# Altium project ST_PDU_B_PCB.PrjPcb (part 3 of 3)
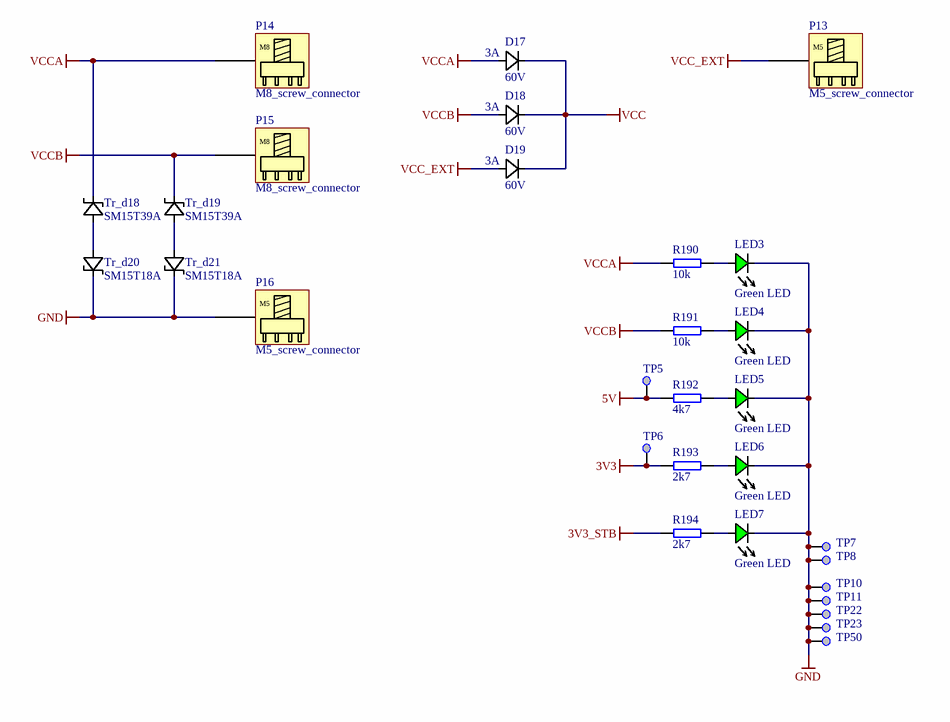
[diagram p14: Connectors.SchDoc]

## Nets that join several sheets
3V3: U_GroupA/U_VNF1248+8F8_A1 (C41A.2 R75A.1 U5A.1), U_GroupA/U_VNF1248+5F8_A1 (C51A.2 R94A.1 U6A.1), U_GroupA/U_VNF1248+3F8_A1 (C31A.2 R55A.1 U4A.1), U_GroupA/U_VNF1248+3F8_A2 (C31B.2 R55B.1 U4B.1), U_GroupA/U_VNF1248+3F8_A3 (C31C.2 R55C.1 U4C.1), U_GroupA/U_VNF9D1M5Q_A1 (C1A.2 D1A.A R1A.1), U_GroupA/U_VNF9D1M5Q_A2 (C1B.2 D1B.A R1B.1), U_GroupA/U_L99SP08_A1 (C58A.2 R101A.1), VNF9Q20SF (C15.2 D5.A R29.1), U_GroupB/U_VNF1248+8F8_B1 (C41B.2 R75B.1 U5B.1), U_GroupB/U_VNF1248+5F8_B1 (C51B.2 R94B.1 U6B.1), U_GroupB/U_VNF1248+3F8_B1 (C31D.2 R55D.1 U4D.1), U_GroupB/U_VNF1248+3F8_B2 (C31E.2 R55E.1 U4E.1), U_GroupB/U_VNF1248+3F8_B3 (C31F.2 R55F.1 U4F.1), U_GroupB/U_VNF9D1M5Q_B1 (C1C.2 D1C.A R1C.1), U_GroupB/U_VNF9D1M5Q_B2 (C1D.2 D1D.A R1D.1), U_GroupB/U_L99SP08_B1 (C58B.2 R101B.1), U_GroupB/U_VNF9D5SF_B1 (C8A.2 D2A.A R15A.1), U_GroupB/U_VNF9D5SF_B2 (C8B.2 D2B.A R15B.1), MCU (7 pins), PMIC (32 pins), Ethernet (18 pins), Connectors (R193.2 TP6.1)
3V3_STB: PMIC (6 pins), Connectors (R194.2)
5V: PMIC (C92.2 U9.3 U9.28), Connectors (R192.1 TP5.1)
GND: U_GroupA/U_VNF1248+8F8_A1 (11 pins), U_GroupA/U_VNF1248+5F8_A1 (11 pins), U_GroupA/U_VNF1248+3F8_A1 (11 pins), U_GroupA/U_VNF1248+3F8_A2 (11 pins), U_GroupA/U_VNF1248+3F8_A3 (11 pins), U_GroupA/U_VNF9D1M5Q_A1 (7 pins), U_GroupA/U_VNF9D1M5Q_A2 (7 pins), U_GroupA/U_L99SP08_A1 (8 pins), VNF9Q20SF (10 pins), U_GroupB/U_VNF1248+8F8_B1 (11 pins), U_GroupB/U_VNF1248+5F8_B1 (11 pins), U_GroupB/U_VNF1248+3F8_B1 (11 pins), U_GroupB/U_VNF1248+3F8_B2 (11 pins), U_GroupB/U_VNF1248+3F8_B3 (11 pins), U_GroupB/U_VNF9D1M5Q_B1 (7 pins), U_GroupB/U_VNF9D1M5Q_B2 (7 pins), U_GroupB/U_L99SP08_B1 (8 pins), U_GroupB/U_VNF9D5SF_B1 (8 pins), U_GroupB/U_VNF9D5SF_B2 (8 pins), MCU (21 pins), PMIC (69 pins), Ethernet (27 pins), Connectors (15 pins)
VCC: PMIC (16 pins), Ethernet (R187.2), Connectors (D17.C D18.C D19.C)
VCC_EXT: MCU (R143.2), Connectors (D19.A P13.1)
VCCA: GroupA (Tr_d3.C Tr_d4.C), U_GroupA/U_VNF1248+8F8_A1 (D9A.A R60A.2), U_GroupA/U_VNF1248+5F8_A1 (D10A.A R82A.2), U_GroupA/U_VNF1248+3F8_A1 (D8A.A R43A.2), U_GroupA/U_VNF1248+3F8_A2 (D8B.A R43B.2), U_GroupA/U_VNF1248+3F8_A3 (D8C.A R43C.2), U_GroupA/U_VNF9D1M5Q_A1 (C3A.2 JP1A.3 JP2A.3 U1A.0), U_GroupA/U_VNF9D1M5Q_A2 (C3B.2 JP1B.3 JP2B.3 U1B.0), U_GroupA/U_L99SP08_A1 (D14A.A), VNF9Q20SF (C17.2 D4.1 U3.0), MCU (R144.2), Connectors (D17.A P14.1 R190.2 Tr_d18.C)
VCCB: GroupB (Tr_d10.C Tr_d13.C), U_GroupB/U_VNF1248+8F8_B1 (D9B.A R60B.2), U_GroupB/U_VNF1248+5F8_B1 (D10B.A R82B.2), U_GroupB/U_VNF1248+3F8_B1 (D8D.A R43D.2), U_GroupB/U_VNF1248+3F8_B2 (D8E.A R43E.2), U_GroupB/U_VNF1248+3F8_B3 (D8F.A R43F.2), U_GroupB/U_VNF9D1M5Q_B1 (C3C.2 JP1C.3 JP2C.3 U1C.0), U_GroupB/U_VNF9D1M5Q_B2 (C3D.2 JP1D.3 JP2D.3 U1D.0), U_GroupB/U_L99SP08_B1 (D14B.A), U_GroupB/U_VNF9D5SF_B1 (C10A.2 D3A.1 U2A.0), U_GroupB/U_VNF9D5SF_B2 (C10B.2 D3B.1 U2B.0), MCU (R145.2), Connectors (D18.A P15.1 R191.2 Tr_d19.C)
CAN1_RX: MCU (U8.2), PMIC (R153.1)
CAN1_TX: MCU (U8.1), PMIC (R152.2)
DI0_A14: U_GroupA/U_L99SP08_A1 (R103A.2), MCU (U8.137)
DI0_B14: U_GroupB/U_L99SP08_B1 (R103B.2), MCU (U8.110)
DI1_A14: U_GroupA/U_L99SP08_A1 (R104A.2), MCU (U8.136)
DI1_B14: U_GroupB/U_L99SP08_B1 (R104B.2), MCU (U8.109)
DI2_A14: U_GroupA/U_L99SP08_A1 (R105A.2), MCU (U8.135)
DI2_B14: U_GroupB/U_L99SP08_B1 (R105B.2), MCU (U8.108)
DI3_A14: U_GroupA/U_L99SP08_A1 (R106A.2), MCU (U8.134)
DI3_B14: U_GroupB/U_L99SP08_B1 (R106B.2), MCU (U8.106)
DI_A1: U_GroupA/U_VNF1248+8F8_A1 (R77A.2), MCU (U8.157)
DI_A2: U_GroupA/U_VNF1248+5F8_A1 (R97A.2), MCU (U8.159)
DI_A3: U_GroupA/U_VNF1248+3F8_A1 (R57A.2), MCU (U8.169)
DI_A4: U_GroupA/U_VNF1248+3F8_A2 (R57B.2), MCU (U8.173)
DI_A5: U_GroupA/U_VNF1248+3F8_A3 (R57C.2), MCU (U8.176)
DI_B1: U_GroupB/U_VNF1248+8F8_B1 (R77B.2), MCU (U8.84)
DI_B2: U_GroupB/U_VNF1248+5F8_B1 (R97B.2), MCU (U8.78)
DI_B3: U_GroupB/U_VNF1248+3F8_B1 (R57D.2), MCU (U8.12)
DI_B4: U_GroupB/U_VNF1248+3F8_B2 (R57E.2), MCU (U8.14)
DI_B5: U_GroupB/U_VNF1248+3F8_B3 (R57F.2), MCU (U8.20)
DIAG_A: U_GroupA/U_VNF1248+8F8_A1 (U5A.6), U_GroupA/U_VNF1248+5F8_A1 (U6A.6), U_GroupA/U_VNF1248+3F8_A1 (U4A.6), U_GroupA/U_VNF1248+3F8_A2 (U4B.6), U_GroupA/U_VNF1248+3F8_A3 (U4C.6), U_GroupA/U_VNF9D1M5Q_A1 (U1A.9 U1A.10), U_GroupA/U_VNF9D1M5Q_A2 (U1B.9 U1B.10), U_GroupA/U_L99SP08_A1 (U7A.1), MCU (D12.C TP21.1), PMIC (D25.1)
DIAG_B: U_GroupB/U_VNF1248+8F8_B1 (U5B.6), U_GroupB/U_VNF1248+5F8_B1 (U6B.6), U_GroupB/U_VNF1248+3F8_B1 (U4D.6), U_GroupB/U_VNF1248+3F8_B2 (U4E.6), U_GroupB/U_VNF1248+3F8_B3 (U4F.6), U_GroupB/U_VNF9D1M5Q_B1 (U1C.9 U1C.10), U_GroupB/U_VNF9D1M5Q_B2 (U1D.9 U1D.10), U_GroupB/U_L99SP08_B1 (U7B.1), MCU (D13.C TP32.1), PMIC (D25.2)
DIAGN: MCU (U8.82), PMIC (U9.15)
EM0_A6: U_GroupA/U_VNF9D1M5Q_A1 (R6A.2), MCU (U8.143)
EM0_A8: U_GroupA/U_VNF9D1M5Q_A2 (R6B.2), MCU (U8.125)
EM0_B6: U_GroupB/U_VNF9D1M5Q_B1 (R6C.2), MCU (U8.87)
EM0_B8: U_GroupB/U_VNF9D1M5Q_B2 (R6D.2), MCU (U8.92)
EM1_A6: U_GroupA/U_VNF9D1M5Q_A1 (R7A.2), MCU (U8.142)
EM1_A8: U_GroupA/U_VNF9D1M5Q_A2 (R7B.2), MCU (U8.124)
EM1_B6: U_GroupB/U_VNF9D1M5Q_B1 (R7C.2), MCU (U8.86)
EM1_B8: U_GroupB/U_VNF9D1M5Q_B2 (R7D.2), MCU (U8.91)
EN_A6: U_GroupA/U_VNF9D1M5Q_A1 (JP2A.2), U_GroupA/U_L99SP08_A1 (U7A.16)
EN_A7: U_GroupA/U_VNF9D1M5Q_A1 (JP1A.2), U_GroupA/U_L99SP08_A1 (U7A.17)
EN_A8: U_GroupA/U_VNF9D1M5Q_A2 (JP2B.2), U_GroupA/U_L99SP08_A1 (U7A.18)
EN_A9: U_GroupA/U_VNF9D1M5Q_A2 (JP1B.2), U_GroupA/U_L99SP08_A1 (U7A.19)
EN_A10: GroupA (D15.1), U_GroupA/U_L99SP08_A1 (U7A.23 U7A.26), VNF9Q20SF (R35.2)
EN_A11: GroupA (D15.2), U_GroupA/U_L99SP08_A1 (U7A.24 U7A.25), VNF9Q20SF (R34.2)
EN_B6: U_GroupB/U_VNF9D1M5Q_B1 (JP2C.2), U_GroupB/U_L99SP08_B1 (U7B.16)
EN_B7: U_GroupB/U_VNF9D1M5Q_B1 (JP1C.2), U_GroupB/U_L99SP08_B1 (U7B.17)
EN_B8: U_GroupB/U_VNF9D1M5Q_B2 (JP2D.2), U_GroupB/U_L99SP08_B1 (U7B.18)
EN_B9: U_GroupB/U_VNF9D1M5Q_B2 (JP1D.2), U_GroupB/U_L99SP08_B1 (U7B.19)
EN_B10: GroupB (D16.2), U_GroupB/U_L99SP08_B1 (U7B.26), U_GroupB/U_VNF9D5SF_B1 (R20A.2)
EN_B11: GroupB (D16.1), U_GroupB/U_L99SP08_B1 (U7B.25), U_GroupB/U_VNF9D5SF_B1 (R21A.2)
EN_B12: GroupB (D27.2), U_GroupB/U_L99SP08_B1 (U7B.24), U_GroupB/U_VNF9D5SF_B2 (R20B.2)
EN_B13: GroupB (D27.1), U_GroupB/U_L99SP08_B1 (U7B.23), U_GroupB/U_VNF9D5SF_B2 (R21B.2)
ETH0_CRS_DV: MCU (U8.166), Ethernet (R180.2 U11.18)
ETH0_MDC: MCU (U8.9), Ethernet (R184.1)
ETH0_MDIO: MCU (U8.8), Ethernet (R181.1 U11.36)
ETH0_REF_CLK: MCU (U8.162), Ethernet (U11.25)
ETH0_RX_ER: MCU (U8.6), Ethernet (R176.2 U11.17)
ETH0_RXD0: MCU (U8.165), Ethernet (R174.2 U11.24)
ETH0_RXD1: MCU (U8.167), Ethernet (R175.2 U11.23)
ETH0_TX_EN: MCU (U8.163), Ethernet (U11.29)
ETH0_TXD0: MCU (U8.161), Ethernet (U11.33)
ETH0_TXD1: MCU (U8.160), Ethernet (U11.32)
ETH_INH: PMIC (D26.2), Ethernet (U11.10)
ETH_PHY_NINT: MCU (U8.116), Ethernet (R186.1)
ETH_PHY_NRST: MCU (U8.11), Ethernet (R185.1)
ETH_PHY_WAKE_IO: MCU (U8.156), Ethernet (R188.1)
FAULT: MCU (U8.174), PMIC (R46.2)
FAULT/NINT: MCU (U8.83), PMIC (U9.16)
HWLO_A1: U_GroupA/U_VNF1248+8F8_A1 (R78A.2), MCU (U8.3)
HWLO_A2: U_GroupA/U_VNF1248+5F8_A1 (R98A.2), MCU (U8.158)
HWLO_A3: U_GroupA/U_VNF1248+3F8_A1 (R58A.2), MCU (U8.168)
HWLO_A4: U_GroupA/U_VNF1248+3F8_A2 (R58B.2), MCU (U8.170)
HWLO_A5: U_GroupA/U_VNF1248+3F8_A3 (R58C.2), MCU (U8.175)
HWLO_B1: U_GroupB/U_VNF1248+8F8_B1 (R78B.2), MCU (U8.81)
HWLO_B2: U_GroupB/U_VNF1248+5F8_B1 (R98B.2), MCU (U8.77)
HWLO_B3: U_GroupB/U_VNF1248+3F8_B1 (R58D.2), MCU (U8.13)
HWLO_B4: U_GroupB/U_VNF1248+3F8_B2 (R58E.2), MCU (U8.15)
HWLO_B5: U_GroupB/U_VNF1248+3F8_B3 (R58F.2), MCU (U8.21)
LH_A6: U_GroupA/U_VNF9D1M5Q_A1 (R10A.2), MCU (U8.152)
LH_A8: U_GroupA/U_VNF9D1M5Q_A2 (R10B.2), MCU (U8.119)
LH_A14: U_GroupA/U_L99SP08_A1 (R102A.2), MCU (U8.138)
LH_B6: U_GroupB/U_VNF9D1M5Q_B1 (R10C.2), MCU (U8.85)
LH_B8: U_GroupB/U_VNF9D1M5Q_B2 (R10D.2), MCU (U8.89)
LH_B14: U_GroupB/U_L99SP08_B1 (R102B.2), MCU (U8.117)
NetR111_2: GroupA (R111.2), U_GroupA/U_L99SP08_A1 (U7A.27)
NetR112_2: GroupA (R112.2), U_GroupA/U_L99SP08_A1 (U7A.28)
NetR113_2: GroupA (R113.2), U_GroupA/U_L99SP08_A1 (U7A.30)
NetR114_2: GroupA (R114.2), U_GroupA/U_L99SP08_A1 (U7A.31)
NetR115_2: GroupB (R115.2), U_GroupB/U_L99SP08_B1 (U7B.27)
NetR116_2: GroupB (R116.2), U_GroupB/U_L99SP08_B1 (U7B.28)
NetR117_2: GroupB (R117.2), U_GroupB/U_L99SP08_B1 (U7B.30)
NetR118_2: GroupB (R118.2), U_GroupB/U_L99SP08_B1 (U7B.31)
NRST: MCU (5 pins), PMIC (U9.23)
OUT_A1: GroupA (P1.1 Tr_d3.A), U_GroupA/U_VNF1248+8F8_A1 (11 pins)
OUT_A2: GroupA (P2.1 Tr_d4.A), U_GroupA/U_VNF1248+5F8_A1 (8 pins)
OUT_A3: GroupA (P3.1), U_GroupA/U_VNF1248+3F8_A1 (6 pins)
OUT_A4: GroupA (P4.1), U_GroupA/U_VNF1248+3F8_A2 (6 pins)
OUT_A5: GroupA (P5.1), U_GroupA/U_VNF1248+3F8_A3 (6 pins)
OUT_A6: GroupA (P6.1), U_GroupA/U_VNF9D1M5Q_A1 (C7A.2 U1A.6), U_GroupA/U_L99SP08_A1 (U7A.11)
OUT_A7: GroupA (P6.3), U_GroupA/U_VNF9D1M5Q_A1 (C6A.2 U1A.5), U_GroupA/U_L99SP08_A1 (U7A.12)
OUT_A8: GroupA (P6.5), U_GroupA/U_VNF9D1M5Q_A2 (C7B.2 U1B.6), U_GroupA/U_L99SP08_A1 (U7A.14)
OUT_A9: GroupA (P6.7), U_GroupA/U_VNF9D1M5Q_A2 (C6B.2 U1B.5), U_GroupA/U_L99SP08_A1 (U7A.15)
OUT_A10: GroupA (P6.2 R114.1), VNF9Q20SF (C22.2 U3.21 U3.22)
OUT_A11: GroupA (P6.4 R113.1), VNF9Q20SF (C21.2 U3.27 U3.28)
OUT_A12: GroupA (P6.6 R112.1), VNF9Q20SF (C20.2 U3.29 U3.30)
OUT_A13: GroupA (P6.8 R111.1), VNF9Q20SF (C23.2 U3.3 U3.4)
OUT_B1: GroupB (P7.1 Tr_d10.A), U_GroupB/U_VNF1248+8F8_B1 (11 pins)
OUT_B2: GroupB (P8.1 Tr_d13.A), U_GroupB/U_VNF1248+5F8_B1 (8 pins)
OUT_B3: GroupB (P9.1), U_GroupB/U_VNF1248+3F8_B1 (6 pins)
OUT_B4: GroupB (P10.1), U_GroupB/U_VNF1248+3F8_B2 (6 pins)
OUT_B5: GroupB (P11.1), U_GroupB/U_VNF1248+3F8_B3 (6 pins)
OUT_B6: GroupB (P12.1), U_GroupB/U_VNF9D1M5Q_B1 (C7C.2 U1C.6), U_GroupB/U_L99SP08_B1 (U7B.11)
OUT_B7: GroupB (P12.3), U_GroupB/U_VNF9D1M5Q_B1 (C6C.2 U1C.5), U_GroupB/U_L99SP08_B1 (U7B.12)
OUT_B8: GroupB (P12.5), U_GroupB/U_VNF9D1M5Q_B2 (C7D.2 U1D.6), U_GroupB/U_L99SP08_B1 (U7B.14)
OUT_B9: GroupB (P12.7), U_GroupB/U_VNF9D1M5Q_B2 (C6D.2 U1D.5), U_GroupB/U_L99SP08_B1 (U7B.15)
OUT_B10: GroupB (P12.2 R118.1), U_GroupB/U_VNF9D5SF_B1 (5 pins)
OUT_B11: GroupB (P12.4 R117.1), U_GroupB/U_VNF9D5SF_B1 (5 pins)
OUT_B12: GroupB (P12.6 R116.1), U_GroupB/U_VNF9D5SF_B2 (5 pins)
OUT_B13: GroupB (P12.8 R115.1), U_GroupB/U_VNF9D5SF_B2 (5 pins)
OUTST_A1: U_GroupA/U_VNF1248+8F8_A1 (R80A.2), MCU (U8.31)
OUTST_A2: U_GroupA/U_VNF1248+5F8_A1 (R99A.2), MCU (U8.32)
OUTST_A3: U_GroupA/U_VNF1248+3F8_A1 (R59A.2), MCU (U8.33)
OUTST_A4: U_GroupA/U_VNF1248+3F8_A2 (R59B.2), MCU (U8.34)
OUTST_A5: U_GroupA/U_VNF1248+3F8_A3 (R59C.2), MCU (U8.35)
OUTST_B1: U_GroupB/U_VNF1248+8F8_B1 (R80B.2), MCU (U8.64)
OUTST_B2: U_GroupB/U_VNF1248+5F8_B1 (R99B.2), MCU (U8.63)
OUTST_B3: U_GroupB/U_VNF1248+3F8_B1 (R59D.2), MCU (U8.62)
OUTST_B4: U_GroupB/U_VNF1248+3F8_B2 (R59E.2), MCU (U8.61)
OUTST_B5: U_GroupB/U_VNF1248+3F8_B3 (R59F.2), MCU (U8.60)
PWM_CLK_A: VNF9Q20SF (R36.2), MCU (U8.141)
PWM_CLK_B: U_GroupB/U_VNF9D5SF_B1 (R22A.2), U_GroupB/U_VNF9D5SF_B2 (R22B.2), MCU (U8.107)
SPI0_CS0: U_GroupA/U_VNF9D1M5Q_A2 (R11B.2), MCU (TP30.1 U8.126)
SPI0_CS1: U_GroupA/U_L99SP08_A1 (R107A.2), MCU (TP29.1 U8.127)
SPI0_CS2: VNF9Q20SF (R38.2), MCU (TP25.1 U8.131)
SPI0_CS6: U_GroupA/U_VNF9D1M5Q_A1 (R11A.2), MCU (TP28.1 U8.128)
SPI0_MISO: U_GroupA/U_VNF9D1M5Q_A1 (R14A.1), U_GroupA/U_VNF9D1M5Q_A2 (R14B.1), VNF9Q20SF (R41.1), MCU (D21.C R124.2 TP24.1)
SPI0_MOSI: U_GroupA/U_VNF9D1M5Q_A1 (R13A.2), U_GroupA/U_VNF9D1M5Q_A2 (R13B.2), U_GroupA/U_L99SP08_A1 (R109A.2), VNF9Q20SF (R40.2), MCU (R125.2 TP26.1)
SPI0_SCK: U_GroupA/U_VNF9D1M5Q_A1 (R12A.2), U_GroupA/U_VNF9D1M5Q_A2 (R12B.2), U_GroupA/U_L99SP08_A1 (R108A.2), VNF9Q20SF (R39.2), MCU (R126.2 TP27.1)
SPI2_CS0: U_GroupB/U_VNF1248+8F8_B1 (R67B.2), MCU (TP46.1 U8.80)
SPI2_CS1: U_GroupB/U_VNF1248+5F8_B1 (R87B.2), MCU (TP45.1 U8.79)
SPI2_CS2: U_GroupB/U_VNF1248+3F8_B3 (R48F.2), MCU (TP42.1 U8.72)
SPI2_CS3: U_GroupB/U_VNF1248+3F8_B1 (R48D.2), MCU (TP44.1 U8.76)
SPI2_CS4: U_GroupB/U_VNF1248+3F8_B2 (R48E.2), MCU (TP43.1 U8.74)
SPI2_MISO: U_GroupB/U_VNF1248+8F8_B1 (R69B.2), U_GroupB/U_VNF1248+5F8_B1 (R89B.2), U_GroupB/U_VNF1248+3F8_B1 (R50D.2), U_GroupB/U_VNF1248+3F8_B2 (R50E.2), U_GroupB/U_VNF1248+3F8_B3 (R50F.2), MCU (D24.C R141.2 TP49.1)
SPI2_MOSI: U_GroupB/U_VNF1248+8F8_B1 (R68B.2), U_GroupB/U_VNF1248+5F8_B1 (R88B.2), U_GroupB/U_VNF1248+3F8_B1 (R49D.2), U_GroupB/U_VNF1248+3F8_B2 (R49E.2), U_GroupB/U_VNF1248+3F8_B3 (R49F.2), MCU (R139.2 TP47.1)
SPI2_SCK: U_GroupB/U_VNF1248+8F8_B1 (R70B.2), U_GroupB/U_VNF1248+5F8_B1 (R90B.2), U_GroupB/U_VNF1248+3F8_B1 (R51D.2), U_GroupB/U_VNF1248+3F8_B2 (R51E.2), U_GroupB/U_VNF1248+3F8_B3 (R51F.2), MCU (R140.2 TP48.1)
SPI3_CS0: MCU (TP36.1 U8.19), PMIC (R159.2)
SPI3_CS6: MCU (TP20.1 U8.172), PMIC (R162.2)
SPI3_MISO: MCU (D22.C R131.1 TP33.1), PMIC (R155.2 R165.2)
SPI3_MOSI: MCU (R132.1 TP34.1), PMIC (R157.1 R163.1)
SPI3_SCK: MCU (R133.1 TP35.1), PMIC (R154.1 R164.1)
SPI5_CS0: U_GroupB/U_VNF9D1M5Q_B1 (R11C.2), MCU (TP9.1 U8.88)
SPI5_CS1: U_GroupB/U_VNF9D5SF_B1 (R24A.2), MCU (TP52.1 U8.94)
SPI5_CS3: U_GroupB/U_L99SP08_B1 (R107B.2), MCU (TP51.1 U8.97)
SPI5_CS5: U_GroupB/U_VNF9D5SF_B2 (R24B.2), MCU (TP53.1 U8.93)
SPI5_CS6: U_GroupB/U_VNF9D1M5Q_B2 (R11D.2), MCU (TP4.1 U8.90)
SPI5_MISO: U_GroupB/U_VNF9D1M5Q_B1 (R14C.1), U_GroupB/U_VNF9D1M5Q_B2 (R14D.1), U_GroupB/U_VNF9D5SF_B1 (R27A.1), U_GroupB/U_VNF9D5SF_B2 (R27B.1), MCU (D23.C R136.2 TP38.1)
SPI5_MOSI: U_GroupB/U_VNF9D1M5Q_B1 (R13C.2), U_GroupB/U_VNF9D1M5Q_B2 (R13D.2), U_GroupB/U_L99SP08_B1 (R109B.2), U_GroupB/U_VNF9D5SF_B1 (R26A.2), U_GroupB/U_VNF9D5SF_B2 (R26B.2), MCU (R137.2 TP39.1)
SPI5_SCK: U_GroupB/U_VNF9D1M5Q_B1 (R12C.2), U_GroupB/U_VNF9D1M5Q_B2 (R12D.2), U_GroupB/U_L99SP08_B1 (R108B.2), U_GroupB/U_VNF9D5SF_B1 (R25A.2), U_GroupB/U_VNF9D5SF_B2 (R25B.2), MCU (R135.2 TP37.1)
SPI9_CS0: U_GroupA/U_VNF1248+5F8_A1 (R87A.2), MCU (TP18.1 U8.147)
SPI9_CS1: U_GroupA/U_VNF1248+8F8_A1 (R67A.2), MCU (TP19.1 U8.146)
SPI9_CS2: U_GroupA/U_VNF1248+3F8_A1 (R48A.2), MCU (TP17.1 U8.148)
SPI9_CS4: U_GroupA/U_VNF1248+3F8_A2 (R48B.2), MCU (TP16.1 U8.150)
SPI9_CS5: U_GroupA/U_VNF1248+3F8_A3 (R48C.2), MCU (TP15.1 U8.151)
SPI9_MISO: U_GroupA/U_VNF1248+8F8_A1 (R69A.2), U_GroupA/U_VNF1248+5F8_A1 (R89A.2), U_GroupA/U_VNF1248+3F8_A1 (R50A.2), U_GroupA/U_VNF1248+3F8_A2 (R50B.2), U_GroupA/U_VNF1248+3F8_A3 (R50C.2), MCU (D20.C R120.2 TP13.1)
SPI9_MOSI: U_GroupA/U_VNF1248+8F8_A1 (R68A.2), U_GroupA/U_VNF1248+5F8_A1 (R88A.2), U_GroupA/U_VNF1248+3F8_A1 (R49A.2), U_GroupA/U_VNF1248+3F8_A2 (R49B.2), U_GroupA/U_VNF1248+3F8_A3 (R49C.2), MCU (R119.2 TP12.1)
SPI9_SCK: U_GroupA/U_VNF1248+8F8_A1 (R70A.2), U_GroupA/U_VNF1248+5F8_A1 (R90A.2), U_GroupA/U_VNF1248+3F8_A1 (R51A.2), U_GroupA/U_VNF1248+3F8_A2 (R51B.2), U_GroupA/U_VNF1248+3F8_A3 (R51C.2), MCU (R121.2 TP14.1)
STDBY_NOT_A: GroupA (D15.3), U_GroupA/U_VNF9D1M5Q_A1 (R5A.2), U_GroupA/U_VNF9D1M5Q_A2 (R5B.2), VNF9Q20SF (R33.2 R37.2), MCU (R204.2)
STDBY_NOT_B: GroupB (D16.3 D27.3), U_GroupB/U_VNF9D1M5Q_B1 (R5C.2), U_GroupB/U_VNF9D1M5Q_B2 (R5D.2), U_GroupB/U_VNF9D5SF_B1 (R19A.2 R23A.2), U_GroupB/U_VNF9D5SF_B2 (R19B.2 R23B.2), MCU (R205.2)
WDI: MCU (U8.4), PMIC (R65.2)
WK_LPM: MCU (U8.5), PMIC (R52.2)

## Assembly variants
SW_DEV: not fitted R44A R44B R44C R44D R44E R44F R53A R53B R53C R53D R53E R53F R61A R61B R62A R62B R63A R63B R66A R66B R74A R74B R79A R79B R81A R81B R83A R83B R86A R86B R95A R95B R100A R100B T4A T4B T4C T4D T4E T4F T6A T6B T6C T6D T6E T6F T7A T7B T8A T8B T9A T9B T10A T10B T12A T12B T13A T13B T14A T14B T15A T15B T16A T16B T18A T18B T19A T19B
Elemaster_Batch_1: not fitted JP6 R71 TP1 TP2 TP3 TP4 TP5 TP6 TP7 TP8 TP9 TP10 TP11 TP12 TP13 TP14 TP15 TP16 TP17 TP18 TP19 TP20 TP21 TP22 TP23 TP24 TP25 TP26 TP27 TP28 TP29 TP30 TP31 TP32 TP33 TP34 TP35 TP36 TP37 TP38 TP39 TP40 TP41 TP42 TP43 TP44 TP45 TP46 TP47 TP48 TP49 TP50 TP51 TP52 TP53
